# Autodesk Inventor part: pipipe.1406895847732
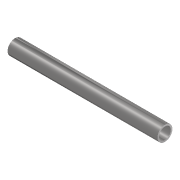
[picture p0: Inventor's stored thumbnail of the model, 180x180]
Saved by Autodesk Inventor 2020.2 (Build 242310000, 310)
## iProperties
Manager: www.cadconsulting.pl
Company: Fabian Stasiak CAD Consulting
IsCustomPart: 1
NAME: PIPING: JIS G 3458 Pipe
DATA: <meta><inlinegroups number="1" deflen="10"></inlinegroups><connections number="2"></connections><angles><a>3.14159265358979</a></angles></meta>
Created: 2014-08
Material: Stal, stopowa
Description: Rura
Document SubType Name: Modeling
Standard: JIS G 3458
Designer: F.Stasiak
Standards Organization: JIS
Language: pl-PL
Size Designation: 40 A x Sch 80 - 100
Categories: <MemberInstance><Categories><Category DisplayName="Rury cienko- i grubościenne" InternalName="4347fa0f-2144-441d-94cd-e3e15c92b736" Mnemonic="TUBEANDPIPE"><Cate
Stock Number: JIS G 3458 Rura 40 A x Sch 80
Density: 7.73 g/cm^3
Appearance: Częściowo polerowana
Catalog Web Link: www.expertbooks.pl
L: 486,000 mm
PL: 486,000 mm
Author: F.Stasiak
Subject: Zbiór ćwiczeń. Autodesk Inventor 2020. Kurs Professional
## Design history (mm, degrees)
sketch "Sketch1"
  geometry: C1 r 24.3 at (0, 0); C2 r 19.2 at (0, 0); 1 further point
  constraints: 2 centre point, 2 coincident, 1 concentric
  dimensions: "d0" = 48.6 diameter of C1 (= OD); "d1" = 38.4 diameter of C2 (= OD - 2 x t)
extrude "Extrusion1" new body sketch "Sketch1" distance "d2" = 486 (= L); taper "d3" = 0 deg
workaxis "Work Axis1"
workpoint "Work Point1"
workaxis "Work Axis2"
workpoint "Work Point2"
body "Solid1"
other parameters: "OD" = 48.6 [user parameter; used in 2 equation terms], "t" = 5.1 [user parameter; used in 1 equation term], "L" = 486 (= PL) [user parameter; used in 1 equation term], "ID" = 38.4 [user parameter], "PL" = 486 [user parameter; used in 1 equation term], "Size_Designation" = 12.345 [user parameter]
